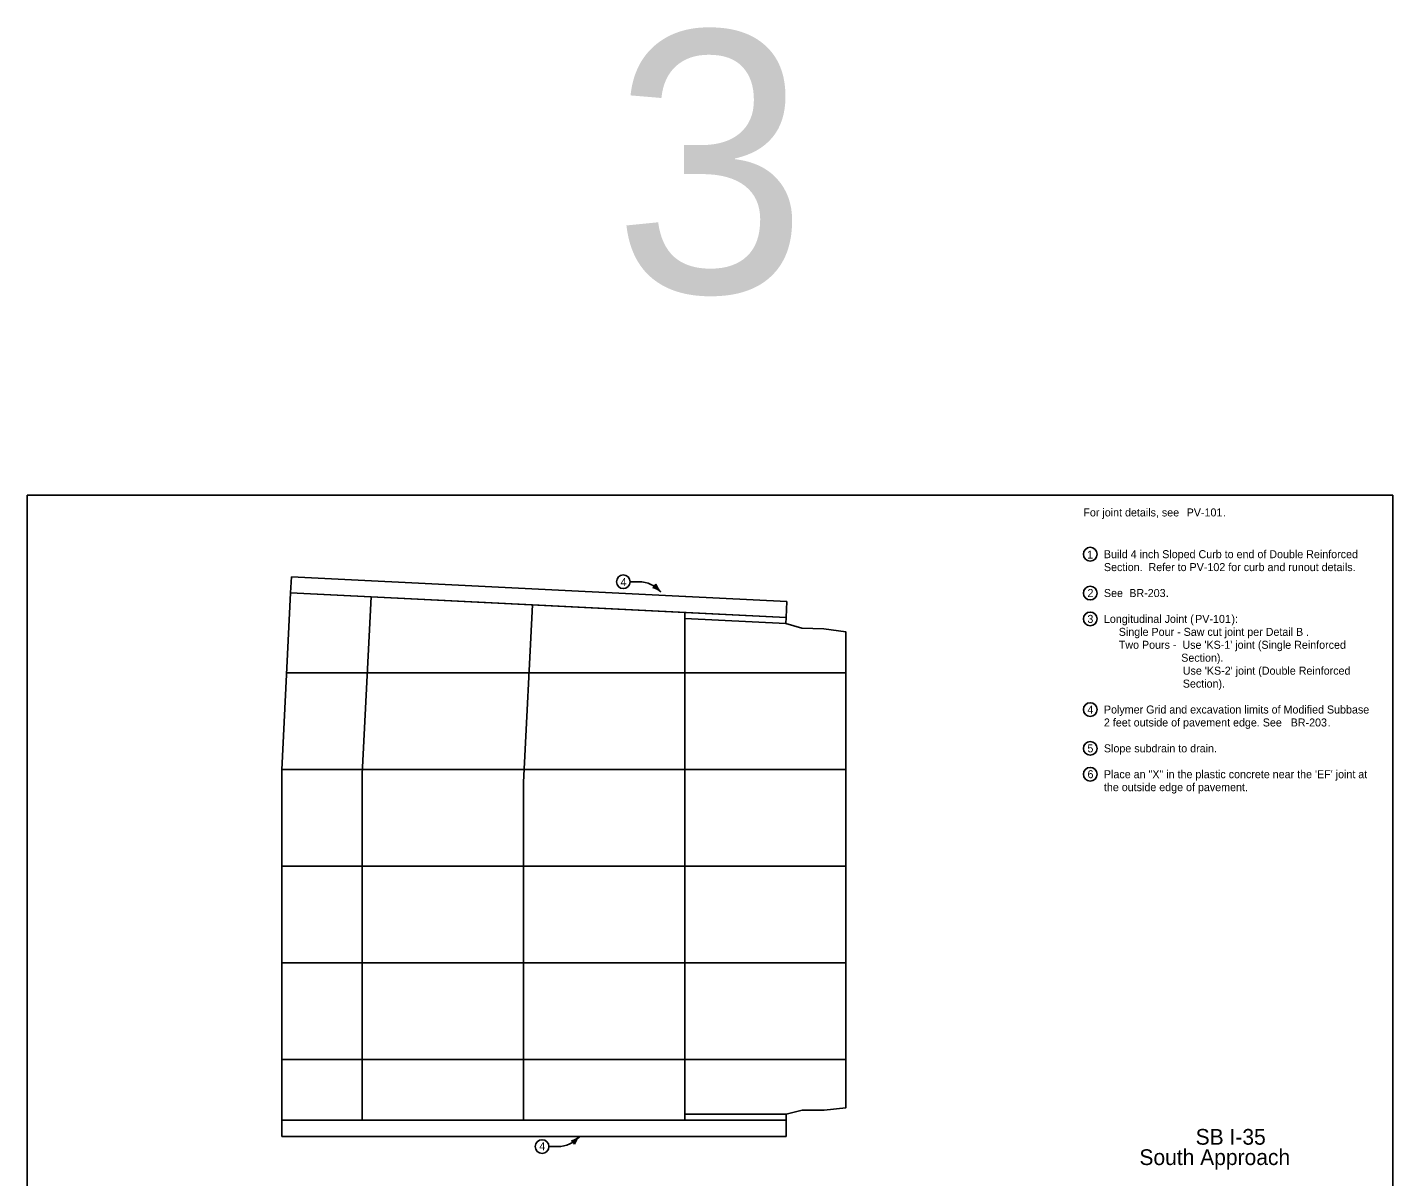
# Model space of a CAD drawing. Extents: x 10045 to 81668, y 6370 to 11018.
# Drawn here: x 17333 to 20468, y 8380 to 11018 of the extents above; entities that cross this region are included whole.
import ezdxf

# ---------------------------------------------------------------- set-up
doc = ezdxf.new("R2010")
doc.units = 0
for name, color, linetype in [('Alignment', 7, 'Continuous'), ('Bridge', 7, 'Continuous'), ('dsnStdLineWork', 7, 'Continuous'), ('LaneLine', 7, 'Continuous'), ('Level 5', 7, 'Continuous'), ('PC_APPROACH', 7, 'Continuous'), ('SheetText', 7, 'Continuous'), ('TextAlignmentLrg', 7, 'Continuous'), ('TextAlignmentSml', 7, 'Continuous')]:
    doc.layers.add(name, color=color, linetype=linetype)

msp = doc.modelspace()

# ---------------------------------------------------------------- linework, layer by layer
at = {"layer": 'Alignment'}
for p, q in [((18736.6, 9745.4), (18716.7, 9745.4)), ((18550.1, 8449.1), (18530.2, 8449.1))]:
    msp.add_line(p, q, dxfattribs=at)
for centre, start, end in [((18736.6, 9678.6), 40.5607, 90), ((18736.6, 9678.6), 40.5607, 90), ((18550.1, 8515.9), 270, 319.4393), ((18550.1, 8515.9), 270, 319.4393)]:
    msp.add_arc(centre, 66.8, start, end, dxfattribs=at)
at = {"layer": 'dsnStdLineWork'}
for p, q in [((17938.9, 9757.1), (17937, 9720.1)), ((18843.7, 9711.9), (17938.9, 9757.1)), ((19076.7, 9700.2), (18844.4, 9711.8)), ((19076.7, 9700.2), (19074.9, 9663.3)), ((17916.7, 8472.5), (17916.7, 8509.5)), ((19074.7, 8472.5), (19074.7, 8509.5)), ((18841.9, 8472.5), (17916.7, 8472.5)), ((19074.7, 8472.5), (18841.9, 8472.5))]:
    msp.add_line(p, q, dxfattribs=at)
for points in [[(17937, 9720.1), (17916.7, 9313.6), (17916.7, 8509.5), (18471.8, 8509.5), (18471.8, 9285.8), (18492.1, 9692.4)], [(18841.9, 9674.9), (18841.9, 8509.5), (19074.7, 8509.5), (19074.7, 8523.3), (19111.7, 8532.6), (19161.8, 8532.6), (19211.9, 8537.6), (19211.9, 9630.8), (19161.5, 9637.4), (19111.2, 9639), (19074.5, 9649.4), (19074.9, 9663.3)]]:
    msp.add_lwpolyline(points, close=True, dxfattribs=at)
for centre in [(19773, 9808.8), (18701, 9745.4), (18701, 9745.4), (19773, 9719.6), (19773, 9660.2), (19773, 9452.2), (19773, 9363.1), (19773, 9303.7), (18514.4, 8449.1), (18514.4, 8449.1)]:
    msp.add_circle(centre, 15.7, dxfattribs=at)
for centre, radius, start, end in [((18760, 9747.3), 17.1, 299.4947, 334.9614), ((18760, 9747.3), 17.1, 299.4947, 334.9614), ((18757.2, 9689.4), 44.4, 47.2281, 75.3006), ((18757.2, 9689.4), 44.4, 47.2281, 75.3006), ((18817.5, 9754.6), 44.4, 199.1556, 227.2281), ((18817.5, 9754.6), 44.4, 199.1556, 227.2281), ((18570.7, 8505.1), 44.4, 284.6994, 312.7719), ((18570.7, 8505.1), 44.4, 284.6994, 312.7719), ((18630.9, 8439.9), 44.4, 132.7719, 160.8444), ((18630.9, 8439.9), 44.4, 132.7719, 160.8444), ((18573.5, 8447.2), 17.1, 25.0386, 60.5053), ((18573.5, 8447.2), 17.1, 25.0386, 60.5053)]:
    msp.add_arc(centre, radius, start, end, dxfattribs=at)
at = {"layer": 'LaneLine'}
msp.add_lwpolyline([(18492.1, 9692.4), (18471.8, 9285.8), (18471.8, 8509.5), (19074.7, 8509.5), (19074.7, 8523.3), (19111.7, 8532.6), (19161.8, 8532.6), (19211.9, 8537.6), (19211.9, 9630.8), (19161.5, 9637.4), (19111.2, 9639), (19074.5, 9649.4), (19074.9, 9663.3)], close=True, dxfattribs=at)
at = {"layer": 'Level 5'}
msp.add_lwpolyline([(17332.5, 9944), (20467.5, 9944), (20467.5, 7924), (17332.5, 7924)], close=True, dxfattribs=at)
at = {"layer": 'PC_APPROACH'}
for p, q in [((17937, 9720.1), (17916.7, 9313.6)), ((18841.9, 9674.9), (17937, 9720.1)), ((19211.9, 8537.6), (19211.9, 9630.8)), ((17916.7, 8509.5), (17916.7, 9313.6)), ((18841.9, 8509.5), (17916.7, 8509.5))]:
    msp.add_line(p, q, dxfattribs=at)
for points in [[(19211.9, 9630.8), (19161.5, 9637.4), (19111.2, 9639), (19074.5, 9649.4), (19074.9, 9663.3)], [(19074.7, 8509.5), (19074.7, 8523.3), (19111.7, 8532.6), (19161.8, 8532.6), (19211.9, 8537.6)]]:
    msp.add_lwpolyline(points, dxfattribs=at)
at = {"layer": 'TextAlignmentLrg'}
for p, q in [((18122.1, 9710.9), (18101.7, 9304.3)), ((18492.1, 9692.4), (18471.8, 9285.8)), ((18841.9, 8509.5), (18841.9, 9674.9)), ((17927.9, 9536.8), (19211.9, 9536.8)), ((17916.7, 9314.7), (19211.9, 9314.7)), ((18101.7, 8509.5), (18101.7, 9304.3)), ((18471.8, 8509.5), (18471.8, 9285.8)), ((17916.7, 9092.7), (19211.9, 9092.7)), ((17916.7, 8870.7), (19211.9, 8870.7)), ((17916.7, 8648.6), (19211.9, 8648.6))]:
    msp.add_line(p, q, dxfattribs=at)
at = {"layer": 'TextAlignmentSml'}
for p, q in [((18841.9, 9661), (18841.9, 9674.9)), ((19074.2, 9649.4), (18841.9, 9661)), ((19074.9, 9663.3), (18842.6, 9674.9)), ((19074.7, 8523.3), (18841.9, 8523.3)), ((18841.9, 8523.3), (18841.9, 8509.5)), ((19074.7, 8509.5), (18841.9, 8509.5))]:
    msp.add_line(p, q, dxfattribs=at)

# ---------------------------------------------------------------- texts
at = {"layer": 'Alignment'}
for s, height, p in [('For joint details, see ', 18.375, (19757.3, 9895.4)), ('PV-101', 18.37, (19994.5, 9895.4)), ('PV-101', 18.37, (19994.5, 9895.4)), ('.', 18.4, (20077.7, 9895.4)), ('1', 18.4, (19765.8, 9798.5)), ('Build 4 inch Sloped Curb to end of Double Reinforced', 18.375, (19804.5, 9799.6)), ('Section.  Refer to PV-102 for curb and runout details.', 18.375, (19804.5, 9769.9)), ('4', 18.4, (18694.6, 9735.6)), ('4', 18.4, (18694.6, 9735.6)), ('2', 18.4, (19766.8, 9710.4)), ('See ', 18.37, (19804.5, 9710.4)), ('BR-203.', 18.37, (19862.8, 9710.4)), ('.', 18.4, (19947.4, 9710.4)), ('3', 18.4, (19766.6, 9651)), ('Longitudinal Joint (', 18.375, (19804.5, 9651)), ('PV-101', 18.37, (20014, 9651)), ('PV-101', 18.37, (20014, 9651)), ('):', 18.37, (20097.3, 9651)), ('     Single Pour - Saw cut joint per Detail B .', 18.375, (19804.5, 9621.3)), ("     Two Pours -  Use 'KS-1' joint (Single Reinforced", 18.375, (19804.5, 9591.6)), ('                          Section).', 18.375, (19804.5, 9561.9)), ("     Use 'KS-2' joint (Double Reinforced", 18.375, (19951.5, 9532.2)), ('     Section).', 18.375, (19951.5, 9502.5)), ('4', 18.4, (19766.6, 9443)), ('Polymer Grid and excavation limits of Modified Subbase', 18.375, (19804.5, 9443)), ('2 feet outside of pavement edge. See ', 18.375, (19804.5, 9413.3)), ('BR-203', 18.37, (20233.3, 9413.3)), ('.', 18.4, (20317.9, 9413.3)), ('5', 18.4, (19766.6, 9353.9)), ('Slope subdrain to drain.', 18.375, (19804.5, 9353.9)), ('6', 18.4, (19766.8, 9294.5)), ('Place an "X" in the plastic concrete near the \'EF\' joint at', 18.375, (19804.5, 9294.5)), ('the outside edge of pavement.', 18.375, (19804.5, 9264.8)), ('4', 18.4, (18508, 8440.6)), ('4', 18.4, (18508, 8440.6))]:
    msp.add_text(s, height=height, dxfattribs=at).set_placement(p)
at = {"layer": 'Bridge'}
for s, height, p in [('SB I-35', 36.09, (20015.1, 8453.3)), ('South Approach', 36.086, (19886, 8406.6))]:
    msp.add_text(s, height=height, dxfattribs=at).set_placement(p)
at = {"layer": 'SheetText'}
msp.add_text('3', height=600, dxfattribs=at).set_placement((18677.6, 10409.2))

doc.saveas('drawing.dxf')
